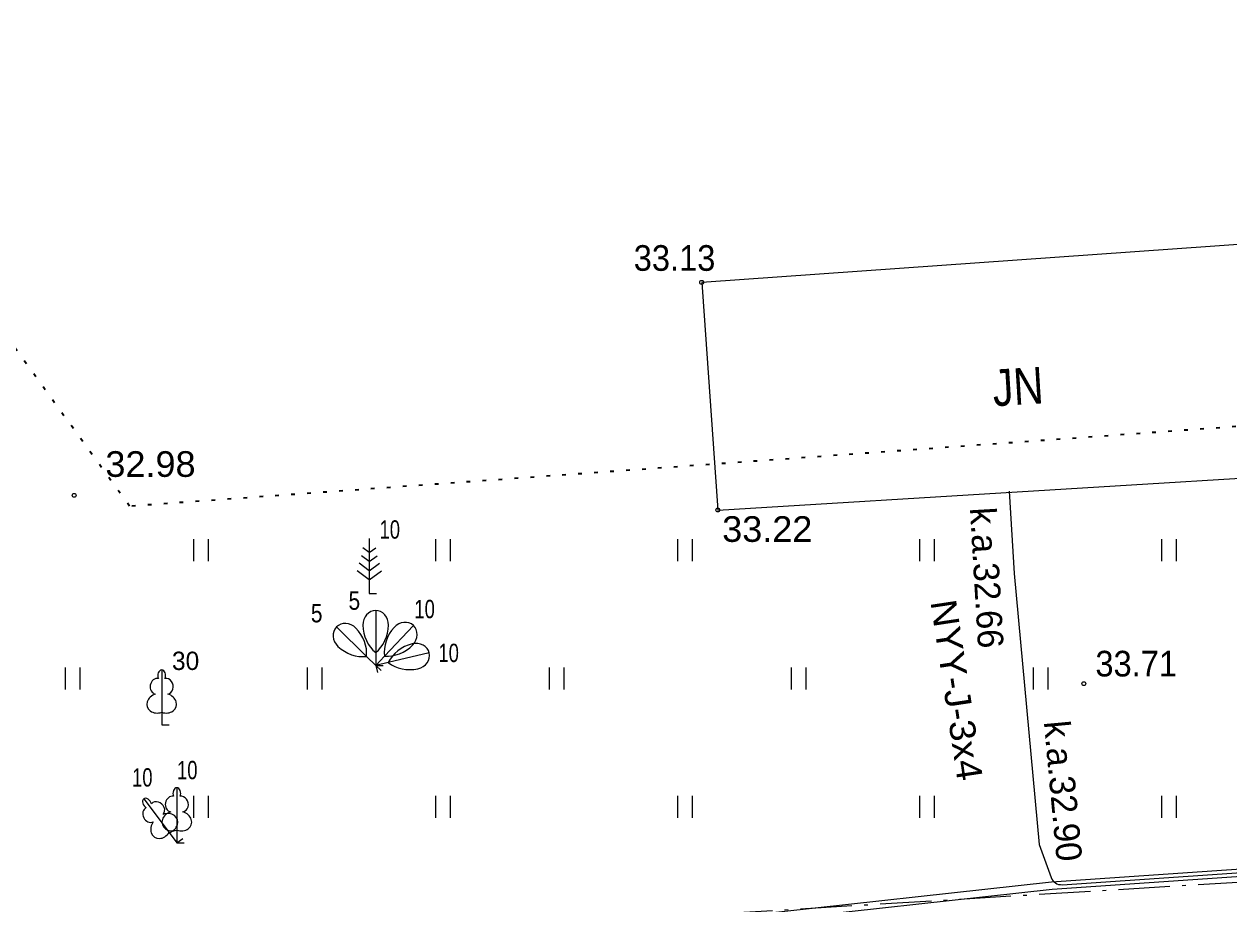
# Model space of a CAD drawing. Extents: x 380758 to 381729, y 283236 to 283533.
# Drawn here: x 381053.95 to 381086.8, y 283342.11 to 283366.12 of the extents above; entities that cross this region are included whole.
import ezdxf

# ---------------------------------------------------------------- set-up
doc = ezdxf.new("R2010")
doc.units = 0
doc.header["$LTSCALE"] = 0.28
doc.linetypes.add('DOT_DASHED', pattern=[7.7, 5, -1.2, 0.3, -1.2])
doc.linetypes.add('DOTTED', pattern=[1.5, 0.3, -1.2])
for name, color, linetype, lineweight in [('1', 7, 'Continuous', 13), ('23', 7, 'Continuous', 13), ('25', 7, 'DOTTED', 35), ('29', 7, 'DOT_DASHED', 25), ('39', 7, 'Continuous', 13), ('4', 7, 'Continuous', 13), ('45', 7, 'Continuous', 13), ('58', 7, 'Continuous', 25), ('7', 7, 'Continuous', 13)]:
    doc.layers.add(name, color=color, linetype=linetype, lineweight=lineweight)

msp = doc.modelspace()

# ---------------------------------------------------------------- linework, layer by layer
at = {"layer": '1'}
for p, q in [((381063.36, 283352.076), (381063.36, 283350.576)), ((381063.36, 283351.7), (381063.184, 283351.828)), ((381063.36, 283351.7), (381063.534, 283351.828)), ((381063.36, 283351.2), (381063.082, 283351.404)), ((381063.36, 283351.45), (381063.144, 283351.608)), ((381063.36, 283351.45), (381063.576, 283351.608)), ((381063.36, 283351.2), (381063.638, 283351.404)), ((381063.36, 283350.95), (381063.028, 283351.194)), ((381063.36, 283350.95), (381063.694, 283351.194)), ((381063.36, 283350.576), (381063.56, 283350.576)), ((381063.535, 283350.115), (381063.535, 283348.967)), ((381064.564, 283349.707), (381063.776, 283348.871)), ((381062.465, 283349.666), (381063.284, 283348.862)), ((381063.284, 283348.862), (381063.535, 283348.615)), ((381063.535, 283348.967), (381063.535, 283348.615)), ((381063.776, 283348.871), (381063.535, 283348.615)), ((381063.535, 283348.615), (381063.675, 283348.758)), ((381063.878, 283348.695), (381063.535, 283348.615)), ((381064.995, 283348.957), (381063.878, 283348.695)), ((381057.698, 283348.492), (381057.698, 283347.339)), ((381063.535, 283348.615), (381063.735, 283348.615)), ((381063.535, 283348.615), (381063.681, 283348.478)), ((381063.535, 283348.615), (381063.581, 283348.42)), ((381057.788, 283348.26), (381057.787, 283348.261)), ((381057.698, 283347.339), (381057.698, 283346.992)), ((381057.698, 283346.992), (381057.898, 283346.992)), ((381058.111, 283345.278), (381058.111, 283344.125)), ((381057.208, 283344.975), (381057.902, 283344.055)), ((381057.419, 283344.844), (381057.418, 283344.844)), ((381058.201, 283345.046), (381058.2, 283345.047)), ((381058.111, 283344.125), (381058.111, 283343.778)), ((381057.902, 283344.055), (381058.111, 283343.778)), ((381058.111, 283343.778), (381058.271, 283343.898)), ((381058.111, 283343.778), (381058.311, 283343.778))]:
    msp.add_line(p, q, dxfattribs=at)
for centre, major_axis, ratio, start_param, end_param in [((381063.535, 283349.715), (0, 0.4), 0.875, 0, 1.5707963), ((381063.535, 283349.715), (0, -0.4), 0.875, 1.5707963, 3.1415927), ((381063.535, 283349.715), (0, -0.4), 0.875, 1.5707963, 3.1415927), ((381062.75, 283349.3856), (0.2854, -0.2802), 0.875, 1.5707963, 3.1415927), ((381062.75, 283349.3856), (0.2854, -0.2802), 0.875, 1.5707963, 3.1415927), ((381064.0103, 283349.7384), (0, -0.9434), 0.875, 4.7372004, 5.6697113), ((381063.0597, 283349.7384), (0, -0.9434), 0.875, 0.613474, 1.5459849), ((381064.2893, 283349.4157), (0.2743, 0.2912), 0.875, 0, 1.5707963), ((381064.2893, 283349.4157), (-0.2743, -0.2912), 0.875, 1.5707963, 3.1415927), ((381064.2893, 283349.4157), (-0.2743, -0.2912), 0.875, 1.5707963, 3.1415927), ((381062.75, 283349.3856), (-0.2854, 0.2802), 0.875, 0, 1.5707963), ((381062.4004, 283349.0628), (0.6733, -0.6609), 0.875, 0.613474, 1.5459849), ((381064.6512, 283349.1068), (-0.6469, -0.6867), 0.875, 4.7372004, 5.6697113), ((381063.0663, 283349.7411), (0.6733, -0.6609), 0.875, 4.7372004, 5.6697113), ((381063.9594, 283349.7586), (-0.6469, -0.6867), 0.875, 0.613474, 1.5459849), ((381064.7372, 283348.4084), (-0.9186, -0.2151), 0.875, 4.7372004, 5.6697113), ((381064.606, 283348.8658), (0.3895, 0.0912), 0.875, 0, 1.5707963), ((381064.5204, 283349.3339), (-0.9186, -0.2151), 0.875, 0.613474, 1.5459849), ((381064.606, 283348.8658), (0.3895, 0.0912), 0.875, 4.712389, 6.2831853), ((381064.606, 283348.8658), (0.3895, 0.0912), 0.875, 4.712389, 6.2831853), ((381057.6984, 283348.3421), (0, -0.1499), 0.707107, 3.1453698, 5.2874846), ((381057.6976, 283348.3421), (0, -0.1499), 0.707107, 0.9957007, 3.1378155), ((381057.5697, 283348.0472), (-0.0387, -0.2124), 0.861323, 3.1415927, 6.2831853), ((381057.8263, 283348.0472), (0.0387, -0.2124), 0.861323, 6.2831853, 9.424778), ((381057.6084, 283347.5849), (0.3068, 0.0951), 0.814445, 1.5707963, 4.7520146), ((381057.7876, 283347.5849), (-0.3068, 0.0951), 0.814445, 1.5311707, 4.712389), ((381058.1114, 283345.1281), (0, -0.1499), 0.707107, 3.1453698, 5.2874846), ((381058.1106, 283345.1281), (0, -0.1499), 0.707107, 0.9957007, 3.1378155), ((381057.2982, 283344.856), (0.0903, -0.1197), 0.707107, 3.1453698, 5.2874846), ((381057.2976, 283344.8555), (0.0903, -0.1197), 0.707107, 0.9957007, 3.1378155), ((381057.5779, 283344.6976), (0.1588, -0.1462), 0.861323, 0, 3.1415927), ((381057.9827, 283344.8332), (-0.0387, -0.2124), 0.861323, 3.1415927, 6.2831853), ((381058.2393, 283344.8332), (0.0387, -0.2124), 0.861323, 6.2831853, 9.424778), ((381057.3731, 283344.5431), (0.097, -0.1929), 0.861323, 3.1415927, 6.2831853), ((381058.0214, 283344.3709), (0.3068, 0.0951), 0.814445, 1.5707963, 4.7520146), ((381057.8254, 283344.3053), (-0.3022, -0.1089), 0.814445, 1.5311707, 4.712389), ((381058.2006, 283344.3709), (-0.3068, 0.0951), 0.814445, 1.5311707, 4.712389), ((381057.6824, 283344.1974), (0.1877, 0.2607), 0.814445, 1.5707963, 4.7520146)]:
    msp.add_ellipse(centre, major_axis=major_axis, ratio=ratio, start_param=start_param, end_param=end_param, dxfattribs=at)
at = {"layer": '23'}
for p, q in [((381058.577, 283351.461), (381058.577, 283352.061)), ((381058.977, 283351.461), (381058.977, 283352.061)), ((381065.177, 283351.461), (381065.177, 283352.061)), ((381065.577, 283351.461), (381065.577, 283352.061)), ((381071.777, 283351.461), (381071.777, 283352.061)), ((381072.177, 283351.461), (381072.177, 283352.061)), ((381078.377, 283351.461), (381078.377, 283352.061)), ((381078.777, 283351.461), (381078.777, 283352.061)), ((381084.977, 283351.461), (381084.977, 283352.061)), ((381085.377, 283351.461), (381085.377, 283352.061)), ((381055.077, 283347.961), (381055.077, 283348.561)), ((381055.477, 283347.961), (381055.477, 283348.561)), ((381061.677, 283347.961), (381061.677, 283348.561)), ((381062.077, 283347.961), (381062.077, 283348.561)), ((381068.277, 283347.961), (381068.277, 283348.561)), ((381068.677, 283347.961), (381068.677, 283348.561)), ((381074.877, 283347.961), (381074.877, 283348.561)), ((381075.277, 283347.961), (381075.277, 283348.561)), ((381081.477, 283347.961), (381081.477, 283348.561)), ((381081.877, 283347.961), (381081.877, 283348.561)), ((381058.577, 283344.461), (381058.577, 283345.061)), ((381058.977, 283344.461), (381058.977, 283345.061)), ((381065.177, 283344.461), (381065.177, 283345.061)), ((381065.577, 283344.461), (381065.577, 283345.061)), ((381071.777, 283344.461), (381071.777, 283345.061)), ((381072.177, 283344.461), (381072.177, 283345.061)), ((381078.377, 283344.461), (381078.377, 283345.061)), ((381078.777, 283344.461), (381078.777, 283345.061)), ((381084.977, 283344.461), (381084.977, 283345.061)), ((381085.377, 283344.461), (381085.377, 283345.061))]:
    msp.add_line(p, q, dxfattribs=at)
at = {"layer": '25'}
msp.add_lwpolyline([(381378.132, 283376.241), (381330.368, 283370.09), (381282.589, 283365.052), (381241.341, 283362.776), (381227.597, 283363.335), (381201.225, 283361.612), (381131.764, 283357.382), (381089.163, 283355.29), (381056.824, 283352.96), (381046.619, 283367.047), (381043.733, 283420.739)], dxfattribs=at)
at = {"layer": '29'}
msp.add_line((381234.784, 283351.686), (381044.752, 283340.119), dxfattribs=at)
at = {"layer": '39'}
msp.add_lwpolyline([(381072.426, 283359.069), (381072.866, 283352.857), (381090.081, 283353.908), (381089.629, 283360.288)], close=True, dxfattribs=at)
at = {"layer": '45'}
msp.add_lwpolyline([(381032.402, 283337.854), (381049.394, 283338.981), (381050.924, 283339.056), (381057.172, 283339.986), (381081.97, 283342.714), (381090.848, 283343.32), (381093.46, 283343.399), (381097.843, 283343.028)], dxfattribs=at)
at = {"layer": '58'}
for centre in [(381072.426, 283359.0691), (381055.311, 283353.2571), (381072.866, 283352.8571), (381082.848, 283348.1181)]:
    msp.add_circle(centre, 0.0534, dxfattribs=at)
at = {"layer": '7'}
for points in [[(381080.814, 283353.371), (381080.945, 283351.128), (381081.629, 283343.726), (381081.955, 283342.83)], [(381050.816, 283338.838), (381057.197, 283339.787), (381081.988, 283342.515), (381090.847, 283343.119), (381098.274, 283342.489), (381113.806, 283343.268)], [(381082.257, 283342.634), (381090.847, 283343.219), (381098.276, 283342.59), (381113.6, 283343.358)]]:
    msp.add_lwpolyline(points, dxfattribs=at)
msp.add_arc((381082.2369, 283342.933), 0.3, 200.00328, 273.90049, dxfattribs=at)

# ---------------------------------------------------------------- texts
at = {"layer": '1'}
for s, width, p in [('10', 0.75, (381063.64, 283352.076)), ('5', 0.85, (381062.794, 283350.135)), ('10', 0.75, (381064.59, 283349.906)), ('5', 0.85, (381061.767, 283349.792)), ('10', 0.75, (381065.246, 283348.708)), ('10', 0.75, (381056.891, 283345.312)), ('10', 0.75, (381058.117, 283345.512))]:
    msp.add_text(s, height=0.5, dxfattribs=dict(at, width=width)).set_placement(p)
msp.add_text('30', height=0.5, dxfattribs=at).set_placement((381057.978, 283348.492))
at = {"layer": '4', "width": 0.85}
msp.add_text('JN', height=1, rotation=3.494, dxfattribs=at).set_placement((381080.386, 283355.686))
at = {"layer": '58'}
for s, width, p in [('33.13', 0.95, (381070.572, 283359.384)), ('32.98', 1.05, (381056.163, 283353.762)), ('33.22', 1.05, (381072.984, 283351.988)), ('33.71', 0.95, (381083.163, 283348.315))]:
    msp.add_text(s, height=0.7, dxfattribs=dict(at, width=width)).set_placement(p)
at = {"layer": '7'}
for s, rotation, p in [('k.a.32.66', 273.349, (381079.74, 283352.912)), ('k.a.32.90', 275.28, (381081.756, 283347.078))]:
    msp.add_text(s, height=0.7, rotation=rotation, dxfattribs=at).set_placement(p)
at = {"layer": '7', "width": 1.1}
msp.add_text('NYY-J-3x4', height=0.7, rotation=278.58, dxfattribs=at).set_placement((381078.662, 283350.355))

doc.saveas('drawing.dxf')
